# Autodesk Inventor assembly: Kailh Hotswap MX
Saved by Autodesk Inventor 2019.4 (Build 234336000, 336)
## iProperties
Created: 2020-04
Part Number: Kailh Hotswap MX
Document SubType Name: Assembly
Designer: Administrator
Title: Kailh Hotswap MX v22
Author: Administrator
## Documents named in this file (3)
- c:\worker\convert-fusion-r03\tmp\job-1\68\output\files\d13246e8-35cd-459e-a921-9df84c55ccbb\36360b22-8850-4f22-92f8-9d8b5b77e727.iam
- c:\worker\convert-fusion-r03\tmp\job-1\68\output\files\d13246e8-35cd-459e-a921-9df84c55ccbb\Component1.ipt
- c:\worker\convert-fusion-r03\tmp\job-1\68\output\files\d13246e8-35cd-459e-a921-9df84c55ccbb\Kailh Hotswap MX v22.ipt
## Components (3 placed, 2 different names)
1. Component1:1
2. Component1:2
3. Kailh Hotswap MX v22
